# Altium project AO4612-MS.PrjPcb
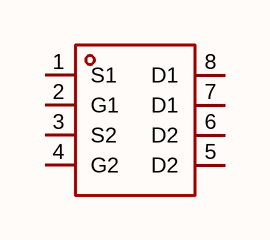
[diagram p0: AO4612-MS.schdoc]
1 sheet, 1 parts. Net scope: global (net labels, ports and power ports of the same name join across sheets).

## Sheet AO4612-MS.schdoc
size 127 x 101 mm

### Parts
Q?  ao4612-ms  [SOP-8_L5.0-W4.0-P1.27-LS6.2-BL]  (value not drawn)

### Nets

Not connected (* = marked no-connect by the designer): Q? 1(S1) 2(G1) 3(S2) 4(G2) 5(D2) 6(D2) 7(D1) 8(D1)

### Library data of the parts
Q? = ao4612-ms: 数量:1个N沟道+1个P沟道;漏源电压(Vdss):60V；60V;连续漏极电流(Id):5A；4A;导通电阻(RDS(on)):60mΩ@10V；100mΩ@10V;耗散功率(Pd):1.5W；1.5W;阈值电压(Vgs(th)):1.2V;; Manufacturer: MSKSEMI(美森科); AddInBom: yes; ModelId: a3315c1c78f949e6bb82c6eaca1c53c7; ModelName: SOP-8_L5.0-W4.0-H1.8-LS6.2-P1.27; ModelTransform: 244.094,196.85,0,90,0,0,0,0,0; Current - Continuous Drain(Id): 5A；4A; Gate Threshold Voltage (Vgs(th)): 1.2V; Gate Charge(Qg): 5.5nC@10V；5.9nC@4.5V; Input Capacitance(Ciss): 695pF；715pF; Reverse Transfer Capacitance (Crss@Vds): 7pF；34pF; Type: N沟道+P沟道; Output Capacitance(Coss): 148pF；51pF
